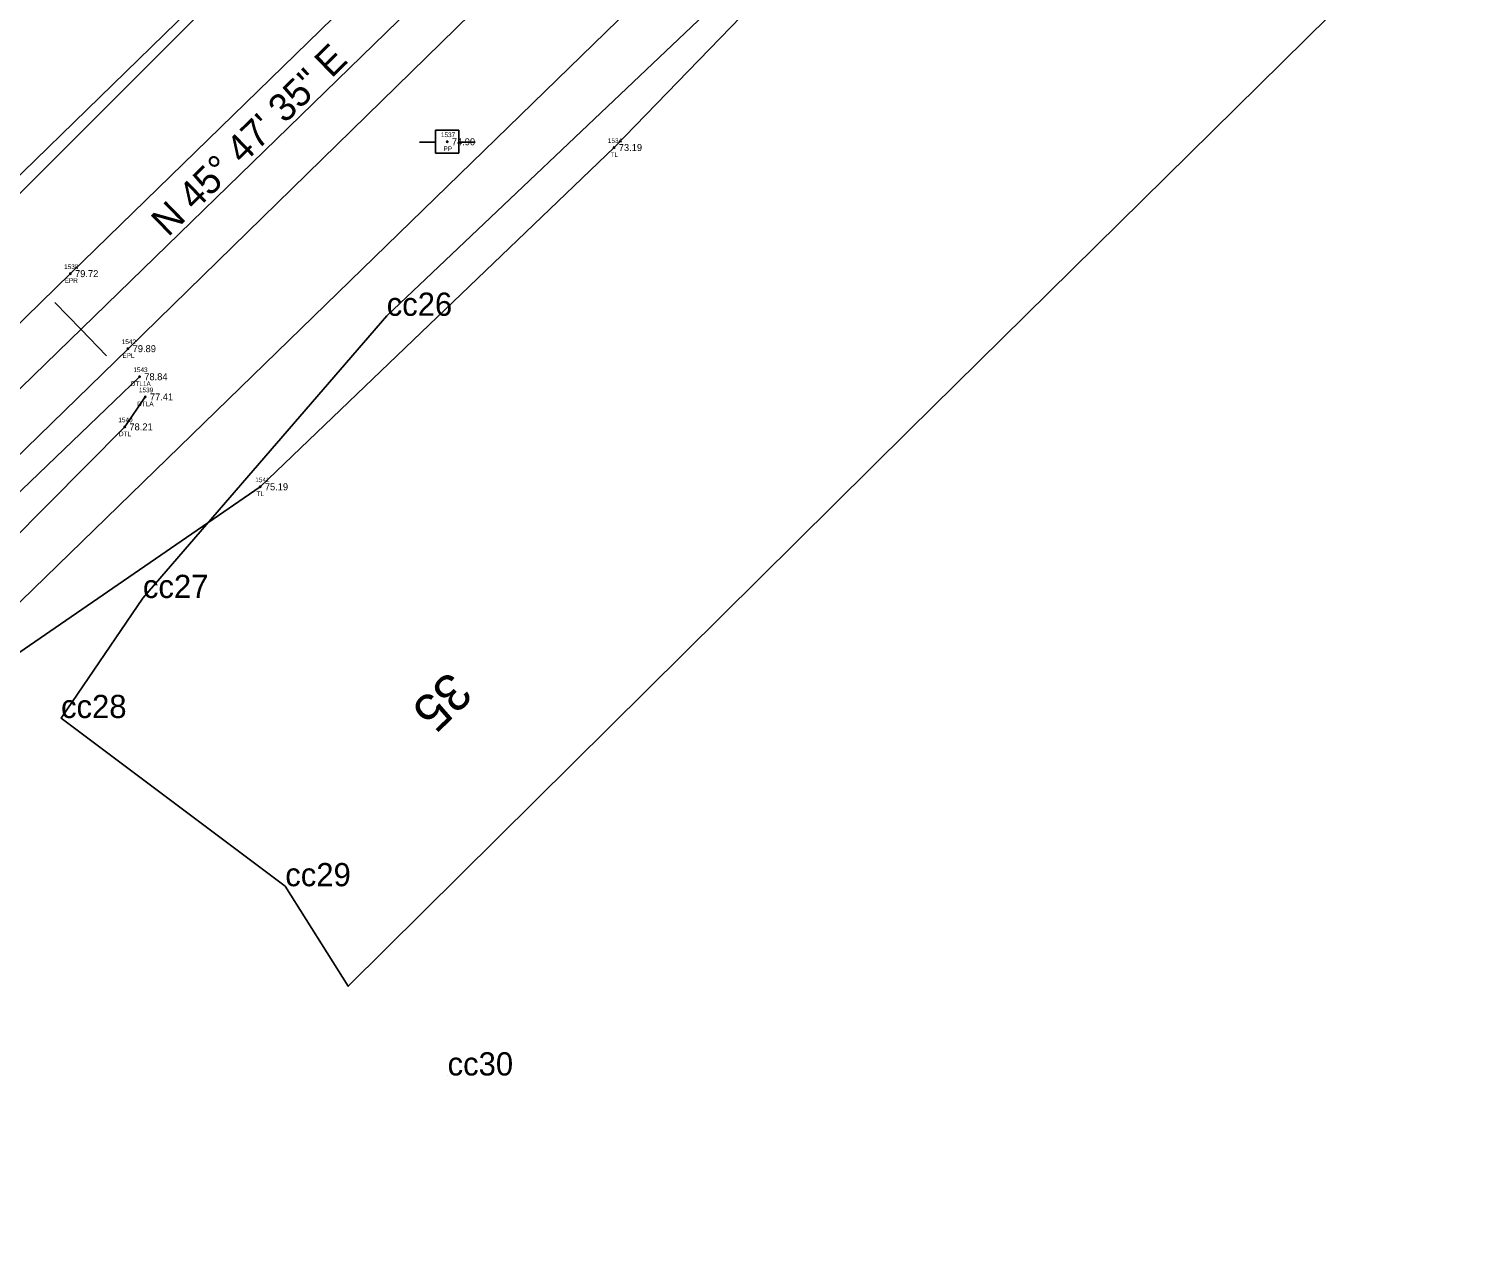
# Model space of a CAD drawing. Extents: x 2500794 to 2511032, y 910653 to 917533.
# Drawn here: x 2505017.8 to 2505331.2, y 912527.6 to 912787.9 of the extents above; entities that cross this region are included whole.
import ezdxf

# ---------------------------------------------------------------- set-up
doc = ezdxf.new("R2010")
doc.units = 0
for name, color, linetype in [('Default', 7, 'Continuous'), ('RD_EX_DV_Prop', 7, 'Continuous'), ('RD_EX_H2O_txCode', 7, 'Continuous'), ('RD_EX_H2O_WetLd', 7, 'Continuous'), ('RD_EX_Road', 7, 'Continuous'), ('RD_EX_Road_txCode', 7, 'Continuous'), ('RD_EX_RW', 7, 'Continuous'), ('RD_EX_TX_H2O_ELEV', 7, 'Continuous'), ('RD_EX_TX_Road_ELEV', 7, 'Continuous'), ('RD_EX_TX_VEG_ELEV', 7, 'Continuous'), ('RD_EX_UT', 7, 'Continuous'), ('RD_EX_UT_txCode', 7, 'Continuous'), ('RD_EX_VEG', 7, 'Continuous'), ('RD_EX_VEG_txCode', 7, 'Continuous'), ('RD_HC_Cl', 7, 'Continuous'), ('RD_HC_Data', 7, 'Continuous'), ('RD_HC_Data_Tic', 7, 'Continuous'), ('RD_HC_Survey_ELEV', 7, 'Continuous'), ('RD_HC_TX_Sta50', 7, 'Continuous'), ('RD_SMD_Locator', 7, 'Continuous')]:
    doc.layers.add(name, color=color, linetype=linetype)

# ---------------------------------------------------------------- blocks, each defined once
blk = doc.blocks.new('POINT_DISPLAY')
at = {"layer": 'Default'}
blk.add_line((0, 0), (0, 0), dxfattribs=at)
blk = doc.blocks.new('Wetlands')
at = {"layer": 'Default'}
blk.add_lwpolyline([(636373.86, 231876.593), (636322.695, 231826.15), (636292.001, 231795.727), (636288.552, 231801.204), (636276.275, 231810.411), (636280.758, 231816.983), (636294.104, 231832.432), (636311.497, 231848.926), (636330.531, 231866.041), (636344.713, 231881.969), (636343.035, 231887.6), (636348.3, 231893.346), (636354.376, 231887.946)], dxfattribs=at)

msp = doc.modelspace()

# ---------------------------------------------------------------- linework, layer by layer
at = {"layer": 'RD_EX_DV_Prop'}
msp.add_line((2503534.53, 911315.65), (2505206.65, 912942.11), dxfattribs=at)
at = {"layer": 'RD_EX_H2O_txCode'}
msp.add_line((2505041.64, 912712.98), (2504976.13, 912650.13), dxfattribs=at)
msp.add_lwpolyline([(2505042.85, 912708.63), (2505038.44, 912702.17), (2504980.48, 912643.76), (2504977.77, 912645.86), (2504976.13, 912650.13)], dxfattribs=at)
at = {"layer": 'RD_EX_Road'}
for points in [[(2505356.25, 913055.37), (2505297.36, 912998.59), (2505254.44, 912956.44), (2505177.06, 912881.21), (2505102.21, 912808.73), (2505026.72, 912735.2), (2504956.07, 912666.21), (2504882.83, 912595.14), (2504825.46, 912547.52), (2504807.83, 912522.24), (2504732.55, 912448.69), (2504654.06, 912372.59), (2504585.1, 912305.45), (2504533.51, 912254.98)], [(2505370.6, 913041.78), (2505311.87, 912984.11), (2505268.01, 912941.43), (2505190.92, 912867.21), (2505116.28, 912794.43), (2505039.14, 912719.03), (2504973.12, 912654.77), (2504957.32, 912639.49), (2504897.44, 912581.22), (2504858.98, 912543.75), (2504838.29, 912523.7), (2504810.7, 912496.65), (2504795.8, 912482.32), (2504747.07, 912434.9), (2504696.6, 912386.17), (2504686.81, 912376.67), (2504668.39, 912358.37), (2504598.36, 912290.29), (2504547.08, 912240.34)]]:
    msp.add_lwpolyline(points, dxfattribs=at)
at = {"layer": 'RD_EX_RW'}
for p, q in [((2504517.34, 912271.63), (2505206.66, 912942.12)), ((2503981.18, 911658.03), (2505252.68, 912894.81))]:
    msp.add_line(p, q, dxfattribs=at)
at = {"layer": 'RD_EX_UT'}
for p, q in [((2505102, 912763.57), (2505105.47, 912763.57)), ((2505110.43, 912766.13), (2505105.43, 912766.13)), ((2505105.43, 912766.13), (2505105.43, 912761.13)), ((2505110.36, 912763.57), (2505114, 912763.57)), ((2505110.43, 912761.13), (2505110.43, 912766.13)), ((2505105.43, 912761.13), (2505110.43, 912761.13))]:
    msp.add_line(p, q, dxfattribs=at)
at = {"layer": 'RD_EX_VEG'}
for points in [[(2505339.13, 913074.53), (2505242.44, 912974.3), (2505088.02, 912824.67), (2504935.82, 912672.7), (2504815.59, 912550.95), (2504817.4, 912591.81)], [(2505299.12, 912922.5), (2505143.93, 912762.37), (2505067.63, 912689.26), (2504988.4, 912634.77), (2505004.57, 912602.97)]]:
    msp.add_lwpolyline(points, dxfattribs=at)
at = {"layer": 'RD_HC_Cl'}
msp.add_line((2504540.35, 912247.97), (2505598.79, 913277.5), dxfattribs=at)
at = {"layer": 'RD_HC_Data_Tic'}
for q in [(2505023.38, 912728.97), (2505034.53, 912717.5)]:
    msp.add_line((2505028.95, 912723.23), q, dxfattribs=at)
at = {"layer": 'RD_SMD_Locator'}
for centre in [(2505107.94, 912763.62), (2505143.93, 912762.37), (2505026.72, 912735.2), (2505039.14, 912719.03), (2505041.64, 912712.98), (2505042.85, 912708.63), (2505038.44, 912702.17), (2505067.63, 912689.26)]:
    msp.add_circle(centre, 0.15, dxfattribs=at)

# ---------------------------------------------------------------- block references
at = {"layer": 'Default', "xscale": 3.937007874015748, "yscale": 3.937007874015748}
for name, p in [('Wetlands', (0, 0)), ('POINT_DISPLAY', (2505094.9, 912726.11)), ('POINT_DISPLAY', (2505094.9, 912726.11)), ('POINT_DISPLAY', (2505042.35, 912665.29)), ('POINT_DISPLAY', (2505042.35, 912665.29)), ('POINT_DISPLAY', (2505024.7, 912639.42)), ('POINT_DISPLAY', (2505024.7, 912639.42)), ('POINT_DISPLAY', (2505073.04, 912603.17)), ('POINT_DISPLAY', (2505073.04, 912603.17)), ('POINT_DISPLAY', (2505108.03, 912562.38)), ('POINT_DISPLAY', (2505108.03, 912562.38))]:
    msp.add_blockref(name, p, dxfattribs=at)
at = {"layer": 'RD_EX_H2O_WetLd', "xscale": 3.937007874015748, "yscale": 3.937007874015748}
msp.add_blockref('Wetlands', (0, 0), dxfattribs=at)

# ---------------------------------------------------------------- texts
at = {"layer": 'Default'}
for s, p in [('cc26', (2505094.9, 912726.11)), ('cc26', (2505094.9, 912726.11)), ('cc27', (2505042.35, 912665.29)), ('cc27', (2505042.35, 912665.29)), ('cc28', (2505024.7, 912639.42)), ('cc28', (2505024.7, 912639.42)), ('cc29', (2505073.04, 912603.17)), ('cc29', (2505073.04, 912603.17)), ('cc30', (2505108.03, 912562.38)), ('cc30', (2505108.03, 912562.38))]:
    msp.add_text(s, height=5, dxfattribs=at).set_placement(p)
at = {"layer": 'RD_EX_H2O_txCode'}
for s, p in [('1543', (2505040.29, 912713.98)), ('DTL1A', (2505039.74, 912710.98)), ('1539', (2505041.5, 912709.63)), ('DTLA', (2505041.12, 912706.63)), ('1540', (2505037.05, 912703.17)), ('DTL', (2505037.19, 912700.17))]:
    msp.add_text(s, height=1, dxfattribs=at).set_placement(p)
at = {"layer": 'RD_EX_Road_txCode'}
for s, p in [('1538', (2505025.37, 912736.2)), ('EPR', (2505025.49, 912733.2)), ('1542', (2505037.79, 912720.03)), ('EPL', (2505037.93, 912717.03))]:
    msp.add_text(s, height=1, dxfattribs=at).set_placement(p)
at = {"layer": 'RD_EX_TX_H2O_ELEV'}
for s, p in [('78.84', (2505042.64, 912712.23)), ('77.41', (2505043.85, 912707.88)), ('78.21', (2505039.44, 912701.42))]:
    msp.add_text(s, height=1.5, dxfattribs=at).set_placement(p)
at = {"layer": 'RD_EX_TX_Road_ELEV'}
for s, p in [('79.72', (2505027.72, 912734.45)), ('79.89', (2505040.14, 912718.28))]:
    msp.add_text(s, height=1.5, dxfattribs=at).set_placement(p)
at = {"layer": 'RD_EX_TX_VEG_ELEV'}
for s, p in [('73.19', (2505144.93, 912761.62)), ('75.19', (2505068.63, 912688.51))]:
    msp.add_text(s, height=1.5, dxfattribs=at).set_placement(p)
at = {"layer": 'RD_EX_UT_txCode'}
for s, p in [('1537', (2505106.59, 912764.62)), ('PP', (2505107.16, 912761.62))]:
    msp.add_text(s, height=1, dxfattribs=at).set_placement(p)
at = {"layer": 'RD_EX_VEG_txCode'}
for s, p in [('1534', (2505142.58, 912763.37)), ('TL', (2505143.16, 912760.37)), ('1541', (2505066.57, 912690.26)), ('TL', (2505066.86, 912687.26))]:
    msp.add_text(s, height=1, dxfattribs=at).set_placement(p)
at = {"layer": 'RD_HC_Data'}
msp.add_text('N 45%%d 47\' 35" E', height=6, rotation=44.2069, dxfattribs=at).set_placement((2505047.79, 912742.95))
at = {"layer": 'RD_HC_Survey_ELEV'}
msp.add_text('74.90', height=1.5, dxfattribs=at).set_placement((2505108.94, 912762.87))
at = {"layer": 'RD_HC_TX_Sta50'}
msp.add_text('35', height=8, rotation=224.2069, dxfattribs=at).set_placement((2505108.39, 912649.83))

doc.saveas('drawing.dxf')
